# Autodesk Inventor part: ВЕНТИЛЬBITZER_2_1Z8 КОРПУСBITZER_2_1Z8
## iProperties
Created: 2011-02
Part Number: ВЕНТИЛЬBITZER_2_1Z8 КОРПУСBITZER_2_1Z8
Document SubType Name: Modeling
Designer: Чернышев Юрий
Mass: 917.249 g
Surface Area: 969.259 cm^2
Volume: 917.249 cm^3
Density: 1 g/cm^3
Author: Чернышев Юрий
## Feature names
1. ExtrusionBlind1
2. ExtrusionBlind2
3. RevolutionAngle1
4. ExtrusionBlind3
5. ExtrusionBlind5
6. ExtrusionBlind6
7. Fillet1
8. Fillet3
9. Hole1
10. Hole2
11. Hole3
12. Hole4
13. Hole5
14. Hole6
15. Hole7
16. Hole8
17. Hole9
18. AM_HOLE_SI0029_1 [Hole]
